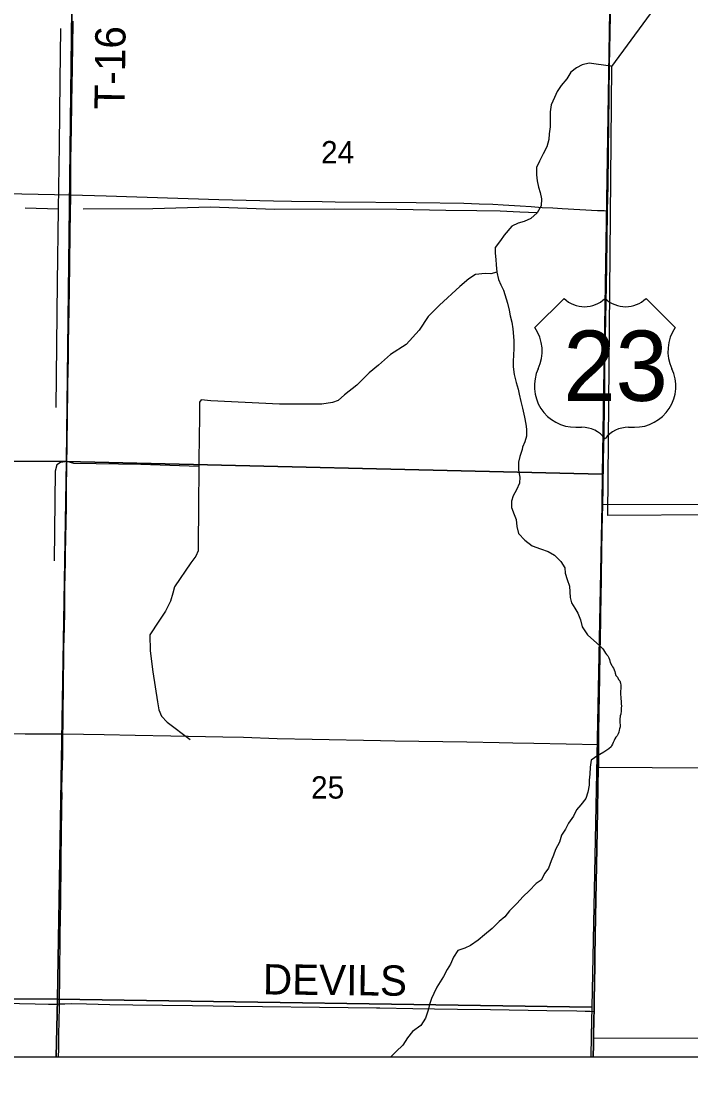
# Model space of a CAD drawing. Extents: x 0 to 34, y 0 to 22.
# Drawn here: x 6.42 to 7.676, y 16.867 to 18.874 of the extents above; entities that cross this region are included whole.
import ezdxf

# ---------------------------------------------------------------- set-up
doc = ezdxf.new("R2010")
doc.units = 0
for name, color, linetype in [('GM_X_Minor_River', 7, 'Continuous'), ('GM_X_Section', 7, 'Continuous'), ('GM_X_Section_Text', 7, 'Continuous'), ('GM_X_State_Route', 7, 'Continuous'), ('GM_X_Township_Road', 7, 'Continuous'), ('GM_X_Township_Road_Text', 7, 'Continuous'), ('GM_X_US_Location', 7, 'Continuous'), ('GM_X_US_Route', 7, 'Continuous'), ('GM_X_US_Shield', 7, 'Continuous'), ('SH_Cut_Line', 7, 'Continuous'), ('SH_Text', 7, 'Continuous')]:
    doc.layers.add(name, color=color, linetype=linetype)

msp = doc.modelspace()

# ---------------------------------------------------------------- linework, layer by layer
at = {"layer": 'GM_X_Minor_River'}
for p, q in [((7.5282, 18.7894), (7.656, 18.9638)), ((7.5206, 17.947), (7.5282, 18.7894)), ((7.5205, 17.9473), (7.5206, 17.9473)), ((7.9171, 17.9505), (7.5206, 17.947))]:
    msp.add_line(p, q, dxfattribs=at)
for points in [[(6.4856, 18.1498), (6.4884, 18.3839), (6.4903, 18.522), (6.4921, 18.6415), (6.4929, 18.7621), (6.4942, 18.8608)], [(7.5264, 18.7901), (7.4991, 18.7939), (7.4855, 18.7954), (7.4726, 18.7926), (7.4618, 18.7868), (7.4514, 18.7784), (7.4439, 18.766), (7.4333, 18.7534), (7.4259, 18.7422), (7.421, 18.7313), (7.4143, 18.7174), (7.4124, 18.7045), (7.4124, 18.6901), (7.4125, 18.6761), (7.4106, 18.6632), (7.4104, 18.6522), (7.4066, 18.6386), (7.3995, 18.6255), (7.3923, 18.6117), (7.3867, 18.5997), (7.3871, 18.586), (7.3884, 18.5746), (7.3904, 18.5631), (7.3939, 18.5532), (7.3966, 18.5413), (7.3955, 18.5277), (7.3884, 18.5146), (7.3764, 18.5043), (7.3638, 18.4985), (7.3527, 18.4954), (7.3404, 18.4896), (7.3264, 18.4732), (7.3197, 18.4628), (7.3095, 18.4501), (7.3096, 18.4395), (7.3109, 18.4273), (7.3114, 18.4174), (7.3125, 18.4037), (7.3156, 18.3896), (7.3203, 18.38), (7.3253, 18.37), (7.3323, 18.3452), (7.3358, 18.3322), (7.3378, 18.3215), (7.3405, 18.3097), (7.3425, 18.2975), (7.3442, 18.2754), (7.3442, 18.261), (7.3435, 18.2474), (7.3429, 18.2375), (7.3433, 18.2258), (7.3453, 18.2117), (7.3487, 18.1968), (7.3525, 18.1842), (7.3542, 18.1746), (7.3576, 18.1609), (7.3607, 18.1483), (7.3645, 18.1315), (7.3668, 18.1185), (7.3685, 18.109), (7.3685, 18.0961), (7.3652, 18.0852), (7.3608, 18.0754)], [(7.5264, 18.7901), (7.5282, 18.7894)], [(7.3884, 18.5146), (7.3559, 18.5161), (7.3188, 18.5178), (7.2749, 18.5185), (7.217, 18.5191), (7.125, 18.5214), (7.0076, 18.5216), (6.8951, 18.5213), (6.7752, 18.5253), (6.6672, 18.5226), (6.5361, 18.5219)], [(6.4903, 18.522), (6.4275, 18.5235)], [(7.3125, 18.4037), (7.3011, 18.4006), (7.2905, 18.4012), (7.2723, 18.399), (7.26, 18.3913), (7.243, 18.3766), (7.205, 18.3418), (7.1836, 18.3207), (7.1667, 18.2946), (7.1426, 18.2682), (7.1129, 18.2492), (7.0905, 18.2292), (7.0731, 18.2149), (7.0498, 18.1919), (7.0266, 18.1735), (7.0146, 18.1631), (7.0043, 18.1592), (6.9841, 18.1559), (6.9046, 18.1563), (6.776, 18.1625), (6.7575, 18.1644), (6.7544, 18.16), (6.7549, 18.1353), (6.7545, 18.1205), (6.7538, 18.1057), (6.7532, 18.0393), (6.7525, 17.963), (6.7523, 17.8925), (6.7523, 17.8811), (6.7476, 17.8713), (6.7381, 17.8583), (6.7079, 17.8135), (6.7049, 17.8014), (6.7, 17.7867), (6.6908, 17.768), (6.6783, 17.7493), (6.6617, 17.7235), (6.6621, 17.6935), (6.6672, 17.6539), (6.676, 17.5979), (6.6783, 17.5827), (6.6833, 17.5708), (6.694, 17.5599), (6.7371, 17.527)], [(7.3608, 18.0754), (7.36, 18.0713), (7.3555, 18.0581), (7.3529, 18.0472), (7.3533, 18.0323), (7.3556, 18.0194), (7.355, 18.0076), (7.3497, 17.9952), (7.3434, 17.984), (7.3401, 17.9742), (7.3398, 17.9621), (7.3448, 17.9491), (7.3491, 17.9395), (7.3503, 17.9269), (7.353, 17.9136), (7.3652, 17.9007), (7.3786, 17.8906), (7.3947, 17.8849), (7.409, 17.8796), (7.4205, 17.8728)], [(6.7532, 18.0393), (6.6447, 18.0431), (6.5186, 18.0446), (6.5066, 18.0483), (6.494, 18.0467), (6.4867, 18.042), (6.4838, 18.0307), (6.4819, 17.8622)], [(7.4205, 17.8728), (7.4324, 17.8612), (7.4404, 17.8492), (7.4409, 17.8393), (7.4444, 17.8275), (7.449, 17.8148), (7.4495, 17.8042), (7.45, 17.7932), (7.4524, 17.7836), (7.4586, 17.7736), (7.4648, 17.764), (7.4694, 17.7514), (7.4729, 17.7384), (7.4824, 17.7233), (7.506, 17.7027)], [(7.506, 17.7027), (7.5111, 17.6978), (7.5126, 17.6951), (7.5145, 17.692), (7.5167, 17.6894), (7.5182, 17.6867), (7.5208, 17.684), (7.5226, 17.6806), (7.5241, 17.6775), (7.5251, 17.6714), (7.5285, 17.6661), (7.5296, 17.6634), (7.5314, 17.6607), (7.5325, 17.6577), (7.534, 17.6546), (7.5343, 17.6516), (7.5358, 17.6474), (7.5391, 17.6443), (7.5409, 17.6397), (7.5436, 17.637), (7.5446, 17.6328), (7.5453, 17.6294), (7.5452, 17.6222), (7.5448, 17.6184), (7.5447, 17.6105), (7.545, 17.6078), (7.5449, 17.604), (7.546, 17.5983), (7.5459, 17.5934), (7.5463, 17.5903), (7.5458, 17.5858), (7.5457, 17.5809), (7.5449, 17.5748), (7.5441, 17.5714), (7.5436, 17.565), (7.5432, 17.5619), (7.5431, 17.5593), (7.5438, 17.5543), (7.5438, 17.5509), (7.5426, 17.5475), (7.5422, 17.5445), (7.5417, 17.5407), (7.5405, 17.5377), (7.5382, 17.5339), (7.5359, 17.5313), (7.534, 17.5283), (7.5328, 17.5253), (7.5305, 17.5215), (7.5293, 17.5185), (7.5278, 17.5156), (7.5268, 17.5135)], [(7.5268, 17.5135), (7.5225, 17.5095), (7.5136, 17.5032), (7.5059, 17.4989), (7.5022, 17.4975)], [(7.5022, 17.4975), (7.4896, 17.4885), (7.4879, 17.4754), (7.4872, 17.4621), (7.4858, 17.4512), (7.4856, 17.4413), (7.4834, 17.4284), (7.4793, 17.4164), (7.4703, 17.4049), (7.4621, 17.3952), (7.4561, 17.3836), (7.4471, 17.3705), (7.4415, 17.3589), (7.434, 17.3481), (7.4299, 17.3349), (7.4224, 17.321), (7.4187, 17.3105), (7.4147, 17.2999), (7.4094, 17.286), (7.4027, 17.2763), (7.396, 17.2636), (7.3863, 17.257), (7.3731, 17.2437), (7.3619, 17.2325), (7.3502, 17.2199), (7.3362, 17.2062), (7.3276, 17.1947), (7.3171, 17.1858), (7.3036, 17.1729), (7.2896, 17.1611), (7.2773, 17.1511), (7.263, 17.1408), (7.2523, 17.1358), (7.2393, 17.1315), (7.2314, 17.1192), (7.2258, 17.1057), (7.2195, 17.0956), (7.2123, 17.0829), (7.2064, 17.0728), (7.1997, 17.0627), (7.1945, 17.051), (7.1901, 17.0413), (7.1864, 17.03), (7.1839, 17.0198), (7.1786, 17.0047), (7.1699, 16.9909), (7.1541, 16.9799), (7.1451, 16.9676), (7.1364, 16.9538), (7.1236, 16.9419), (7.1139, 16.9319), (7.1139, 16.9319)]]:
    msp.add_lwpolyline(points, dxfattribs=at)
at = {"layer": 'GM_X_Section'}
for points in [[(6.5168, 19.0579), (6.5049, 18.0487), (5.5052, 18.0545), (5.5091, 19.0615)], [(7.5264, 19.0334), (7.5252, 18.9738), (7.5101, 18.0247), (6.5049, 18.0487), (6.5168, 19.0579)], [(6.5049, 18.0487), (6.488, 17.04), (5.4985, 17.0434), (5.5052, 18.0545)], [(7.5101, 18.0247), (7.5093, 17.9678), (7.4907, 17.0255), (6.488, 17.04), (6.5049, 18.0487)]]:
    msp.add_lwpolyline(points, close=True, dxfattribs=at)
for points in [[(6.4705, 16.1819), (6.4673, 16.0279), (6.437, 16.0283), (5.476, 16.0344), (5.4985, 17.0434), (6.488, 17.04), (6.4858, 16.9319)], [(6.4858, 16.9319), (6.488, 17.04), (7.4907, 17.0255), (7.4897, 16.9717), (7.489, 16.9319)]]:
    msp.add_lwpolyline(points, dxfattribs=at)
at = {"layer": 'GM_X_State_Route'}
for points in [[(6.3156, 17.5391), (6.4274, 17.538), (6.479, 17.5378), (6.4984, 17.5376), (6.5759, 17.5366), (6.6337, 17.5356), (6.7008, 17.5342), (6.7984, 17.532), (6.8375, 17.5315), (6.9003, 17.5293), (6.966, 17.5277), (7.094, 17.5256), (7.1213, 17.5249), (7.2561, 17.5228), (7.3167, 17.5214), (7.3428, 17.5211), (7.382, 17.5202), (7.4429, 17.519), (7.5035, 17.5176)], [(7.5035, 17.5176), (7.5034, 17.501), (7.5033, 17.4881), (7.5031, 17.4755)], [(7.5031, 17.4755), (7.7045, 17.4738), (7.9348, 17.4725), (8.0957, 17.4713), (8.3231, 17.4688), (8.4251, 17.4674), (8.4546, 17.4677), (8.6481, 17.4781), (8.7174, 17.4818), (8.9, 17.4864)]]:
    msp.add_lwpolyline(points, dxfattribs=at)
at = {"layer": 'GM_X_Township_Road'}
for p, q in [((7.5111, 17.9676), (8.4557, 17.9711)), ((7.4942, 16.968), (8.6621, 16.9631))]:
    msp.add_line(p, q, dxfattribs=at)
for points in [[(6.513, 18.5485), (6.5135, 18.6076), (6.5141, 18.6499), (6.5143, 18.6667), (6.5153, 18.7257), (6.5157, 18.7512), (6.5168, 18.8264), (6.5175, 18.8743)], [(5.5074, 18.5595), (5.5171, 18.5594), (5.6053, 18.5585), (5.6352, 18.5584), (5.6868, 18.5577), (5.7246, 18.557), (5.7918, 18.5562), (5.8334, 18.5559), (5.8618, 18.5558), (5.9202, 18.5552), (6.001, 18.5543), (6.0893, 18.5536), (6.1304, 18.5532), (6.1789, 18.553), (6.2243, 18.5531), (6.3138, 18.5524), (6.3909, 18.5512), (6.513, 18.5485)], [(6.4984, 17.5376), (6.4989, 17.553), (6.4988, 17.5629), (6.4989, 17.5894), (6.4991, 17.5983), (6.4992, 17.6054), (6.4995, 17.6292), (6.5001, 17.6869), (6.5003, 17.7004), (6.5006, 17.7153), (6.5017, 17.7635), (6.5017, 17.7801), (6.5019, 17.7932), (6.5022, 17.8136), (6.5026, 17.8347), (6.5034, 17.8619), (6.5035, 17.8779), (6.5038, 17.9034), (6.5043, 17.9364), (6.5049, 17.9625), (6.5054, 17.9998), (6.506, 18.0389), (6.507, 18.1285), (6.5072, 18.1484), (6.5075, 18.1658), (6.5076, 18.1757), (6.5078, 18.1931), (6.5087, 18.2433), (6.5091, 18.2707), (6.5101, 18.3335), (6.5107, 18.3714), (6.5113, 18.4168), (6.5121, 18.4796), (6.513, 18.5467), (6.513, 18.5485)], [(6.513, 18.5485), (6.5793, 18.5469), (6.791, 18.5399), (6.8934, 18.5375), (6.927, 18.5369), (6.9848, 18.5359), (7.009, 18.5357), (7.1614, 18.534), (7.2503, 18.5328), (7.2794, 18.532), (7.3052, 18.5309), (7.3244, 18.5297), (7.3561, 18.528), (7.3771, 18.5267), (7.3975, 18.5251), (7.4174, 18.524), (7.4354, 18.523), (7.5012, 18.5195), (7.5137, 18.519), (7.52, 18.5187)], [(6.4919, 17.0313), (6.4924, 17.0866), (6.4927, 17.1068), (6.4934, 17.1379), (6.4934, 17.1596), (6.4938, 17.1938), (6.4942, 17.2202), (6.4947, 17.2451), (6.495, 17.2746), (6.4953, 17.3166), (6.4954, 17.3368), (6.4957, 17.3522), (6.4958, 17.368), (6.4961, 17.3815), (6.4965, 17.4063), (6.4968, 17.4219), (6.4966, 17.4343), (6.4972, 17.4595), (6.4976, 17.4782), (6.4979, 17.497), (6.4981, 17.5123), (6.4979, 17.5285), (6.4984, 17.5376)], [(5.4947, 17.038), (5.5107, 17.038), (5.548, 17.038), (5.5822, 17.038), (5.6755, 17.0381), (5.7252, 17.0381), (5.7905, 17.0376), (5.8526, 17.0374), (5.9024, 17.0377), (5.9366, 17.0373), (5.977, 17.0369), (6.0578, 17.036), (6.1075, 17.0354), (6.1697, 17.0349), (6.2225, 17.0345), (6.2909, 17.0337), (6.3437, 17.0332), (6.3872, 17.0325), (6.4463, 17.0314), (6.4711, 17.0309), (6.4866, 17.031), (6.4919, 17.0313)], [(6.4901, 16.9319), (6.4904, 16.9466), (6.4909, 16.9731), (6.4918, 17.0259), (6.4919, 17.0313)], [(6.4919, 17.0313), (6.4959, 17.0316), (6.5021, 17.0318), (6.5146, 17.0319), (6.5426, 17.0313), (6.5861, 17.03), (6.6296, 17.0294), (6.6855, 17.0287), (6.7415, 17.0281), (6.8192, 17.027), (7.0337, 17.0249), (7.0865, 17.0241), (7.0927, 17.024), (7.1549, 17.0229), (7.1953, 17.0222), (7.2388, 17.0217), (7.3009, 17.0207), (7.4066, 17.019), (7.4625, 17.0182), (7.4781, 17.018), (7.4874, 17.0177), (7.4951, 17.0174)]]:
    msp.add_lwpolyline(points, dxfattribs=at)
at = {"layer": 'GM_X_US_Route'}
for points in [[(7.5263, 18.9541), (7.5247, 18.8516), (7.5236, 18.7926), (7.5229, 18.7366), (7.5222, 18.6822), (7.5213, 18.6278), (7.5206, 18.5657), (7.5198, 18.5192), (7.5197, 18.5175), (7.518, 18.4134), (7.5171, 18.3466), (7.5158, 18.2844), (7.5146, 18.2316), (7.5145, 18.2239), (7.5146, 18.2208), (7.5145, 18.2161), (7.5146, 18.213), (7.5144, 18.1975), (7.5144, 18.1835), (7.5138, 18.1508), (7.513, 18.0996), (7.5122, 18.0514), (7.5114, 17.9986), (7.5109, 17.9681), (7.5109, 17.9675), (7.5098, 17.9209), (7.5084, 17.8354), (7.5075, 17.7873), (7.5073, 17.7686), (7.5071, 17.75), (7.506, 17.6894), (7.5052, 17.6443), (7.504, 17.576), (7.5036, 17.5419), (7.5033, 17.5181), (7.5032, 17.5015), (7.5031, 17.4886), (7.5029, 17.4761), (7.5005, 17.3565), (7.4984, 17.2259), (7.4977, 17.1948), (7.4972, 17.1591), (7.4966, 17.1202), (7.4964, 17.1016), (7.4958, 17.072), (7.4954, 17.0378), (7.4949, 17.018), (7.4946, 17.0052), (7.494, 16.9686), (7.4938, 16.9555), (7.4934, 16.9319)], [(7.4934, 16.9319), (7.4938, 16.9555), (7.494, 16.9686), (7.4946, 17.0052), (7.4949, 17.018), (7.4954, 17.0378), (7.4958, 17.072), (7.4964, 17.1016), (7.4966, 17.1202), (7.4972, 17.1591), (7.4977, 17.1948), (7.4984, 17.2259), (7.5005, 17.3565), (7.5029, 17.4761), (7.5031, 17.4886), (7.5032, 17.5015), (7.5033, 17.5181), (7.5036, 17.5419), (7.504, 17.576), (7.5052, 17.6443), (7.506, 17.6894), (7.5071, 17.75), (7.5073, 17.7686), (7.5075, 17.7873), (7.5084, 17.8354), (7.5098, 17.9209), (7.5109, 17.9675), (7.5109, 17.9681), (7.5114, 17.9986), (7.5122, 18.0514), (7.513, 18.0996), (7.5138, 18.1508), (7.5144, 18.1835), (7.5144, 18.1975), (7.5146, 18.213), (7.5145, 18.2161), (7.5146, 18.2208), (7.5145, 18.2239), (7.5146, 18.2316), (7.5158, 18.2844), (7.5171, 18.3466), (7.518, 18.4134), (7.5197, 18.5175), (7.5198, 18.5192), (7.5206, 18.5657), (7.5213, 18.6278), (7.5222, 18.6822), (7.5229, 18.7366), (7.5236, 18.7926), (7.5247, 18.8516), (7.5263, 18.9541)], [(7.5035, 17.5176), (7.5038, 17.5413), (7.5042, 17.5754), (7.5055, 17.6438), (7.5062, 17.6888), (7.5074, 17.7494), (7.5075, 17.7681), (7.5077, 17.7867), (7.5086, 17.8349), (7.5101, 17.9203), (7.5111, 17.9669), (7.5111, 17.9676), (7.5117, 17.998), (7.5125, 18.0508), (7.5132, 18.099), (7.514, 18.1503), (7.5147, 18.1829), (7.5146, 18.1969), (7.5148, 18.2124), (7.5147, 18.2155), (7.5148, 18.2202), (7.5147, 18.2233), (7.5148, 18.2311), (7.516, 18.2839), (7.5173, 18.346), (7.5182, 18.4129), (7.52, 18.517), (7.52, 18.5187), (7.5208, 18.5651), (7.5215, 18.6273), (7.5224, 18.6817), (7.5231, 18.7361), (7.5238, 18.792), (7.5249, 18.851), (7.5266, 18.9536)], [(7.5031, 17.4755), (7.5033, 17.4881), (7.5034, 17.501), (7.5035, 17.5176)], [(7.4936, 16.9319), (7.494, 16.9549), (7.4942, 16.968), (7.4948, 17.0047), (7.4951, 17.0174), (7.4956, 17.0373), (7.4961, 17.0715), (7.4966, 17.101), (7.4968, 17.1197), (7.4975, 17.1585), (7.4979, 17.1943), (7.4986, 17.2253), (7.5007, 17.3559), (7.5031, 17.4755)]]:
    msp.add_lwpolyline(points, dxfattribs=at)
at = {"layer": 'GM_X_US_Shield'}
for p, q in [((7.4387, 18.3545), (7.3838, 18.2996)), ((7.6474, 18.2996), (7.5925, 18.3545)), ((7.4607, 18.1128), (7.4717, 18.1128)), ((7.5595, 18.1128), (7.5705, 18.1128))]:
    msp.add_line(p, q, dxfattribs=at)
for centre, radius, start, end in [((7.4771, 18.3937), 0.0549, 225.573, 314.427), ((7.5541, 18.3937), 0.0549, 225.573, 314.427), ((7.3208, 18.2555), 0.0769, 334.5471, 35.0009), ((7.7104, 18.2555), 0.0769, 144.9991, 205.4529), ((7.4598, 18.1897), 0.0769, 154.8319, 270.6383), ((7.5714, 18.1897), 0.0769, 269.3617, 25.1681), ((7.4717, 18.0579), 0.0549, 36.8699, 90), ((7.5595, 18.0579), 0.0549, 90, 143.1301)]:
    msp.add_arc(centre, radius, start, end, dxfattribs=at)
at = {"layer": 'SH_Cut_Line'}
for points in [[(7.4934, 16.9319), (7.4938, 16.9555), (7.494, 16.9686), (7.4946, 17.0052), (7.4949, 17.018), (7.4954, 17.0378), (7.4958, 17.072), (7.4964, 17.1016), (7.4966, 17.1202), (7.4972, 17.1591), (7.4977, 17.1948), (7.4984, 17.2259), (7.5005, 17.3565), (7.5029, 17.4761), (7.5031, 17.4886), (7.5032, 17.5015), (7.5033, 17.5181), (7.5036, 17.5419), (7.504, 17.576), (7.5052, 17.6443), (7.506, 17.6894), (7.5071, 17.75), (7.5073, 17.7686), (7.5075, 17.7873), (7.5084, 17.8354), (7.5098, 17.9209), (7.5109, 17.9675), (7.5109, 17.9681), (7.5114, 17.9986), (7.5122, 18.0514), (7.513, 18.0996), (7.5138, 18.1508), (7.5144, 18.1835), (7.5144, 18.1975), (7.5146, 18.213), (7.5145, 18.2161), (7.5146, 18.2208), (7.5145, 18.2239), (7.5146, 18.2316), (7.5158, 18.2844), (7.5171, 18.3466), (7.518, 18.4134), (7.5197, 18.5175), (7.5198, 18.5192), (7.5206, 18.5657), (7.5213, 18.6278), (7.5222, 18.6822), (7.5229, 18.7366), (7.5236, 18.7926), (7.5247, 18.8516), (7.5263, 18.9541)], [(7.5263, 18.9541), (7.5247, 18.8516), (7.5236, 18.7926), (7.5229, 18.7366), (7.5222, 18.6822), (7.5213, 18.6278), (7.5206, 18.5657), (7.5198, 18.5192), (7.5197, 18.5175), (7.518, 18.4134), (7.5171, 18.3466), (7.5158, 18.2844), (7.5146, 18.2316), (7.5145, 18.2239), (7.5146, 18.2208), (7.5145, 18.2161), (7.5146, 18.213), (7.5144, 18.1975), (7.5144, 18.1835), (7.5138, 18.1508), (7.513, 18.0996), (7.5122, 18.0514), (7.5114, 17.9986), (7.5109, 17.9681), (7.5109, 17.9675), (7.5098, 17.9209), (7.5084, 17.8354), (7.5075, 17.7873), (7.5073, 17.7686), (7.5071, 17.75), (7.506, 17.6894), (7.5052, 17.6443), (7.504, 17.576), (7.5036, 17.5419), (7.5033, 17.5181), (7.5032, 17.5015), (7.5031, 17.4886), (7.5029, 17.4761), (7.5005, 17.3565), (7.4984, 17.2259), (7.4977, 17.1948), (7.4972, 17.1591), (7.4966, 17.1202), (7.4964, 17.1016), (7.4958, 17.072), (7.4954, 17.0378), (7.4949, 17.018), (7.4946, 17.0052), (7.494, 16.9686), (7.4938, 16.9555), (7.4934, 16.9319)]]:
    msp.add_lwpolyline(points, dxfattribs=at)
at = {"layer": 'SH_Text'}
msp.add_lwpolyline([(5.7647, 16.9319), (7.7647, 16.9319), (7.7647, 16.1819), (5.7647, 16.1819)], close=True, dxfattribs=at)

# ---------------------------------------------------------------- texts
at = {"layer": 'GM_X_Section_Text'}
for s, p in [('24', (6.9827, 18.6076)), ('25', (6.9639, 17.4164))]:
    msp.add_text(s, height=0.04186, rotation=0, dxfattribs=at).set_placement(p)
at = {"layer": 'GM_X_Township_Road_Text'}
for s, rotation, p in [('T-16', 89.3208, (6.6142, 18.7085)), ('DEVILS', 359.4218, (6.8734, 17.0492))]:
    msp.add_text(s, height=0.05682, rotation=rotation, dxfattribs=at).set_placement(p)
at = {"layer": 'GM_X_US_Location'}
for s in ['0', '/']:
    msp.add_text(s, height=0.000189, dxfattribs=at).set_placement((7.5155, 18.2271))
msp.add_text('23', height=0.000189, rotation=0, dxfattribs=at).set_placement((7.4764, 18.1879))
at = {"layer": 'GM_X_US_Shield'}
msp.add_text('23', height=0.13184, dxfattribs=at).set_placement((7.4373, 18.1622))

doc.saveas('drawing.dxf')
